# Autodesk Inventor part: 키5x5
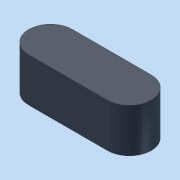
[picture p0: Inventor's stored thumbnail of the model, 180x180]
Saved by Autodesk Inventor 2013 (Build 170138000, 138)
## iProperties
Company: 한국ATC센터
Created: 2014-12
Part Number: 키5x5
Document SubType Name: Modeling
Designer: KYOUNG IL JANG
Density: 1 g/cm^3
Mass: 0.323175 g
Surface Area: 2.9781 cm^2
Volume: 0.323175 cm^3
Material: 일반
Author: KYOUNG IL JANG
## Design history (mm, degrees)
sketch "스케치1"
  geometry: L1 (-4.5, -2.5)-(4.5, -2.5) reference; L2 (4.5, 2.5)-(-4.5, 2.5) reference; A1 r 2.5 centre (-4.5, 0) between (-4.5, 2.5) and (-4.5, -2.5) reference; A2 r 2.5 centre (4.5, 0) between (4.5, -2.5) and (4.5, 2.5) reference; 1 further point
extrude "돌출1" new body sketch "스케치1" distance "d0" = 5; taper "d1" = 0 deg
node "솔리드1"
node "참조1"
